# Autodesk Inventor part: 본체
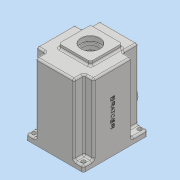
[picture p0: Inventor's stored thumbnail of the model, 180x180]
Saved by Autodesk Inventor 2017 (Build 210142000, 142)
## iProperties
Part Number: 본체
Material: 일반
Document SubType Name: Modeling
Designer: MRC
Density: 1 g/cm^3
Appearance: 기본값
Author: MRC
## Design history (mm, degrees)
sketch "스케치1"
  geometry: L1 (-49, 60)-(49, 60); L2 (49, 60)-(49, -50); L3 (49, -50)-(-49, -50); L4 (-49, -50)-(-49, 60); 2 further points
  constraints: 8 end point, 2 parallel, 1 horizontal, 1 midpoint, 1 perpendicular, 1 vertical alignment
  dimensions: "d0" = 50 distance from line of L3 point (0, 0); "d1" = 110 distance of L1.end L2.end; "d2" = 98 distance of L2.end L3.end
extrude "돌출1" new body sketch "스케치1" stored distance "d3" = 130; taper "d4" = 0 deg
sketch "스케치2"
  geometry: L1 (49, 60)-(-49, 60) reference; L2 (-49, -50)-(49, -50) reference; L3 (49, -50)-(49, 60) reference; L4 (33, 60)-(33, 33); L5 (33, 33)-(49, 33); L6 (49, -33)-(33, -33); L7 (33, -33)-(33, -50); 1 further point
  constraints: 8 end point, 4 point on line, 3 perpendicular, 1 horizontal
  dimensions: "d5" = 16 distance of L4.end L5.end; "d6" = 27 distance of L4.start L4.end; "d7" = 17 distance of L6.end L7.end; "d8" = 16 distance of L6.start L6.end
extrude "돌출2" cut sketch "스케치2" distance "d9" = 120; taper "d10" = 0 deg
sketch "스케치3"
  geometry: L1 (-27, 38)-(27, 38); L2 (27, 38)-(27, -16); L3 (27, -16)-(-27, -16); L4 (-27, -16)-(-27, 38); 2 further points
  constraints: 8 end point, 2 parallel, 1 horizontal, 1 midpoint, 1 perpendicular, 1 vertical alignment
  dimensions: "d87" = 54 distance of L2.end L3.end; "d88" = 54 distance of L1.end L2.end
extrude "돌출12" join sketch "스케치3" distance "d90" = 7; taper "d91" = 0 deg
sketch "스케치4"
  geometry: L1 (-23, 53)-(23, 53); L2 (23, 53)-(23, 38.678); L3 (-23, 53)-(-23, 38.678); A1 r 45 centre (0, 0) between (-23, 38.678) and (23, 38.678); 2 further points
  constraints: 6 end point, 2 point on circle, 2 vertical, 1 centre point, 1 coincident, 1 horizontal, 1 midpoint, 1 vertical alignment
  dimensions: "d15" = 90 diameter of A1; "d16" = 46 distance of L1.start L1.end; "d17" = 53 distance from line of point (0, 0) L1
extrude "돌출4" cut sketch "스케치4" distance "d18" = 9; taper "d19" = 0 deg
sketch "스케치5"
  geometry: L1 (-23, 53)-(23, 53) reference; L2 (-23, 38.678)-(-23, 53) reference; L3 (23, 53)-(23, 38.678) reference; L4 (-23, 53)-(23, 53) reference; L5 (-23, 38.678)-(-23, 53) reference; L6 (23, 53)-(23, 38.678) reference; L7 (20, 50)-(-20, 50); L8 (-20, 50)-(-20, 36.932); L9 (20, 36.932)-(20, 50); A1 r 45 centre (0, 0) between (-23, 38.678) and (23, 38.678) reference; A2 r 45 centre (0, 0) between (-23, 38.678) and (23, 38.678) reference; A3 r 42 centre (0, 0) between (-20, 36.932) and (20, 36.932)
  constraints: 6 end point, 2 point on circle, 1 centre point, 3 other
  dimensions: "d20" = 3 distance between parallel lines of L1 L7
extrude "돌출5" cut sketch "스케치5" distance "d21" = 112; taper "d22" = 0 deg
sketch "스케치6"
  geometry: A1 r 42 centre (0, 0) between (-20, 36.932) and (20, 36.932) reference; A2 r 21 centre (0, 11) between (8.978, -7.984) and (-8.978, -7.984); A3 r 15 centre (0, -20) between (-8.978, -7.984) and (8.978, -7.984)
  constraints: 4 point on circle, 2 centre point, 2 vertical alignment
  dimensions: "d23" = 42 diameter of A2; "d24" = 11 distance of A1.centre A2.centre; "d25" = 30 diameter of A3; "d26" = 20 distance of A3.centre A1.centre
extrude "돌출6" join sketch "스케치6" distance "d27" = 7; taper "d28" = 0 deg
sketch "스케치7"
  geometry: C1 r 17.5 at (0, 11); A1 r 21 centre (0, 11) between (8.978, -7.984) and (-8.978, -7.984) reference; 1 further point
  constraints: 1 centre point, 1 coincident
  dimensions: "d29" = 35 diameter of C1
extrude "돌출7" cut sketch "스케치7" distance "d30" = 10; taper "d31" = 0 deg
sketch "스케치8"
  geometry: C1 r 17.5 at (0, 0) reference; C2 r 14 at (0, 0); 1 further point
  constraints: 1 centre point, 1 coincident
  dimensions: "d32" = 28 diameter of C2
extrude "돌출8" cut sketch "스케치8" stored distance "d33" = 10; taper "d34" = 0 deg
sketch "스케치9"
  geometry: C1 r 11 at (0, -20); A1 r 15 centre (0, -20) between (-8.978, -7.984) and (8.978, -7.984) reference; 1 further point
  constraints: 1 centre point, 1 coincident
  dimensions: "d35" = 22 diameter of C1
extrude "돌출9" cut sketch "스케치9" distance "d36" = 7; taper "d37" = 0 deg
sketch "스케치10"
  geometry: C1 r 11 at (0, 0) reference; C2 r 9.5 at (0, 0); 1 further point
  constraints: 1 centre point, 1 coincident
  dimensions: "d38" = 19 diameter of C2
extrude "돌출10" cut sketch "스케치10" distance "d39" = 3; taper "d40" = 0 deg
fillet "모깎기1" dims "d41" = 3
fillet "모깎기2" dims "d42" = 0.3
chamfer "모따기1" distance "d43" = 1; stored, may be unused: second distance "d44" = 2, angle "d45" = 45 deg
chamfer "모따기2" distance "d46" = 1; stored, may be unused: second distance "d47" = 2, angle "d48" = 45 deg
fillet "모깎기3" dims "d49" = 0.3
sketch "스케치13"
  geometry: L1 (-20, 36.932)-(-20, 50) reference; L2 (20, 50)-(20, 36.932) reference; L3 (-35.777, 4)-(-41.809, 4); L4 (-35.777, -4)-(-41.809, -4); A1 r 36 centre (0, 0) between (-36, 0) and (-35.777, 4); A2 r 4 centre (-36, 0) between (-36, -4) and (-36, 4); A3 r 42 centre (0, 0) between (-41.809, 4) and (-41.809, -4); A4 r 42 centre (0, 0) between (20, 36.932) and (-20, 36.932); 2 further points
  constraints: 9 point on circle, 6 end point, 4 centre point, 2 coincident, 2 horizontal, 2 point on line, 2 tangent, 1 horizontal alignment
  dimensions: "d57" = 72 diameter of A1; "d58" = 8 diameter of A2
extrude "돌출11" join sketch "스케치13" stored distance "d60" = 3; taper "d61" = 0 deg
hole "구멍1" diameter "d64" = 3.242; stored, may be unused: countersink angle "d68" = 90 deg, drill point angle "d70" = 118 deg; dims "d62" = 10, "d63" = 10, "d65" = 7, "d66" = 4, "d67" = 2, "d69" = 9
hole "구멍2" diameter "d73" = 3.242; stored, may be unused: countersink angle "d77" = 90 deg, drill point angle "d79" = 118 deg; dims "d71" = 10, "d72" = 10, "d74" = 7, "d75" = 4, "d76" = 2, "d78" = 9
fillet "모깎기6" dims "d80" = 6
fillet "모깎기7" dims "d81" = 3
fillet "모깎기8" dims "d82" = 3
chamfer "모따기3" distance "d83" = 1; stored, may be unused: second distance "d84" = 2, angle "d85" = 45 deg
fillet "모깎기9" dims "d86" = 3
sketch "스케치15"
  geometry: L1 (11, 63.7)-(11, 72); L2 (11, 72)-(27.462, 72); L3 (-3, 72)-(25, 72) reference; L4 (27.462, 72)-(27, 71.2); L5 (27, 71.2)-(27, 63.7); L6 (27, 63.7)-(11, 63.7); L7 (38, 72)-(-16, 72) reference; 1 further point
  constraints: 10 end point, 1 collinear, 1 midpoint, 1 parallel, 1 perpendicular, 1 point on line, 1 vertical
  dimensions: "d94" = 8.3 distance between parallel lines of L2 L6; "d95" = 0.8 vertical distance of L2.end L4.end; "d96" = 30 deg angle of L5 L4; "d97" = 32 diameter of L5 L1
revolve "회전2" sketch "스케치15" stored, may be unused: angle "d98" = 90 deg
fillet "모깎기10" dims "d99" = 0.3
fillet "모깎기11" dims "d100" = 3
fillet "모깎기12" dims "d101" = 3
fillet "모깎기13" dims "d102" = 3
sketch "스케치16"
  geometry: L1 (-49, 57)-(-49, -47) reference; L2 (46, 60)-(-46, 60) reference; L3 (-46, -50)-(46, -50) reference; L4 (49, -47)-(49, 57) reference; C1 r 3.5 at (-42, 53); C2 r 3.5 at (-42, -43); C3 r 3.5 at (42, -43); C4 r 3.5 at (42, 53)
  constraints: 4 centre point
  dimensions: "d104" = 7 diameter of C1; "d105" = 7 distance from line of L2 C1.centre; "d106" = 7 distance from line of L1 C1.centre; "d109" = 7 diameter of C2; "d110" = 7 diameter of C3; "d111" = 7 diameter of C4; "d112" = 7 distance from line of L3 C2.centre; "d113" = 7 distance from line of L1 C2.centre; "d114" = 7 distance from line of L3 C3.centre; "d115" = 7 distance from line of C3.centre L4; "d116" = 7 distance from line of L2 C4.centre; "d117" = 7 distance from line of L4 C4.centre
extrude "돌출14" cut sketch "스케치16" stored distance "d118" = 7; taper "d119" = 0 deg
sketch "스케치17"
  geometry: L1 (0, 0)-(92, 0) reference; C1 r 22.5 at (46, -40); 2 further points
  constraints: 1 centre point, 1 midpoint, 1 vertical alignment
  dimensions: "d120" = 45 diameter of C1; "d121" = 40 distance from line of L1 C1.centre
extrude "돌출15" join sketch "스케치17" distance "d122" = 10; taper "d123" = 0 deg
sketch "스케치18"
  geometry: C1 r 22.5 at (46, -40) reference; C2 r 15 at (46, -89); 1 further point
  constraints: 1 centre point, 1 vertical alignment
  dimensions: "d124" = 30 diameter of C2; "d125" = 49 distance of C2.centre C1.centre
extrude "돌출16" join sketch "스케치18" distance "d126" = 5; taper "d127" = 0 deg
hole "구멍3" diameter "d130" = 33.376; stored, may be unused: countersink angle "d134" = 90 deg, drill point angle "d136" = 118 deg; dims "d128" = 10, "d129" = 10, "d131" = 70, "d132" = 4, "d133" = 2, "d135" = 77.3
sketch "스케치20"
  geometry: C1 r 15 at (17, 80) reference; C2 r 15 at (17, 80); 1 further point
  constraints: 1 centre point, 1 coincident
  dimensions: "d137" = 30 diameter of C2
extrude "돌출17" cut sketch "스케치20" distance "d138" = 5; taper "d139" = 0 deg
chamfer "모따기4" distance "d140" = 1; stored, may be unused: second distance "d141" = 2, angle "d142" = 45 deg
sketch "스케치21"
  geometry: C1 r 15 at (0, 0) reference; C2 r 10 at (0, 0); 1 further point
  constraints: 1 centre point, 1 coincident
  dimensions: "d143" = 20 diameter of C2
extrude "돌출18" cut sketch "스케치21" stored distance "d144" = 5; taper "d145" = 0 deg
fillet "모깎기15" dims "d146" = 3
sketch "스케치22"
  geometry: L1 (-130, 104)-(-130, 83) reference; 2 further points
  constraints: 2 coincident, 1 other
  dimensions: "d147" = 65 distance from line of L1 point (-65, 47) (derived)
feature "엠보싱1" sketch "스케치22" dims "d10" = 0, "d148" = 0.5, "d149" = 0
node "솔리드1"
mirror "미러1"
mirror "미러2"
node "투영된 루프1"
